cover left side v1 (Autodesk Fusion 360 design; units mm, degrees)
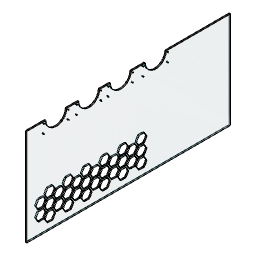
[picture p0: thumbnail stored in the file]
sketch "Sketch1" plane through (0, 0, 0) normal (1, 0, 0) x axis (0, 1, 0)
  line L1 (-390, -185) -> (-390, 185)
  line L2 (390, -185) -> (-390, -185)
  line L3 (390, 185) -> (390, -185)
  line L4 (-317, 185) -> (-390, 185)
  line L5 (-191, 185) -> (-237, 185)
  line L6 (-70, 185) -> (-111, 185)
  line L7 (64, 185) -> (10, 185)
  line L8 (390, 185) -> (144, 185)
  line L9 (-319.9278, -100.8334) -> (-309.9359, -83.5082)
  line L10 (-344.9359, -63.5082) -> (-324.9359, -63.4989)
  line L11 (-324.9197, -138.1399) -> (-344.9197, -138.1492)
  line L12 (-279.9278, -140.8147) -> (-289.9197, -158.1399)
  line L13 (-289.9359, -123.4989) -> (-279.9278, -140.8147)
  line L14 (25.0803, -98.1399) -> (5.0803, -98.1492)
  line L15 (-344.9359, -63.5082) -> (-324.9359, -63.4989)
  line L16 (-64.9197, -98.1492) -> (-74.9278, -80.8334)
  line L17 (-169.9197, -158.1492) -> (-179.9278, -140.8334)
  line L18 (5.0641, -103.5082) -> (25.0641, -103.4989)
  line L19 (-39.9278, -100.8334) -> (-29.9359, -83.5082)
  line L20 (-34.9278, -80.8147) -> (-44.9197, -98.1399)
  line L21 (-174.9278, -120.8147) -> (-184.9197, -138.1399)
  line L22 (-319.9278, -60.8334) -> (-309.9359, -43.5082)
  line L23 (-244.9278, -120.8147) -> (-254.9197, -138.1399)
  line L24 (-214.9278, -120.8334) -> (-204.9359, -103.5082)
  line L25 (-289.9197, -158.1399) -> (-309.9197, -158.1492)
  line L26 (-354.9278, -80.8334) -> (-344.9359, -63.5082)
  line L27 (-354.9278, -80.8334) -> (-344.9359, -63.5082)
  line L28 (-34.9278, -80.8147) -> (-44.9197, -98.1399)
  line L29 (-284.9278, -80.8334) -> (-274.9359, -63.5082)
  line L30 (-99.9359, -123.5082) -> (-79.9359, -123.4989)
  line L31 (-309.9197, -78.1492) -> (-319.9278, -60.8334)
  line L32 (-274.9197, -138.1492) -> (-284.9278, -120.8334)
  line L33 (-309.9359, -83.5082) -> (-289.9359, -83.4989)
  line L34 (-79.9359, -83.4989) -> (-69.9278, -100.8147)
  line L35 (-209.9278, -140.8147) -> (-219.9197, -158.1399)
  line L36 (-44.9359, -63.4989) -> (-34.9278, -80.8147)
  line L37 (-64.9359, -63.5082) -> (-44.9359, -63.4989)
  line L38 (-174.9278, -80.8147) -> (-184.9197, -98.1399)
  line L39 (-184.9359, -103.4989) -> (-174.9278, -120.8147)
  line L40 (-324.9197, -98.1399) -> (-344.9197, -98.1492)
  line L41 (-344.9359, -103.5082) -> (-324.9359, -103.4989)
  line L42 (-219.9197, -158.1399) -> (-239.9197, -158.1492)
  line L43 (25.0803, -138.1399) -> (5.0803, -138.1492)
  line L44 (60.0803, -158.1399) -> (40.0803, -158.1492)
  line L45 (-314.9278, -120.8147) -> (-324.9197, -138.1399)
  line L46 (-219.9197, -118.1399) -> (-239.9197, -118.1492)
  line L47 (-324.9359, -63.4989) -> (-314.9278, -80.8147)
  line L48 (-74.9278, -80.8334) -> (-64.9359, -63.5082)
  line L49 (-209.9278, -140.8147) -> (-219.9197, -158.1399)
  line L50 (-284.9278, -120.8334) -> (-274.9359, -103.5082)
  line L51 (-239.9197, -118.1492) -> (-249.9278, -100.8334)
  line L52 (40.0803, -158.1492) -> (30.0722, -140.8334)
  line L53 (-74.9278, -80.8334) -> (-64.9359, -63.5082)
  line L54 (-79.9359, -43.4989) -> (-69.9278, -60.8147)
  line L55 (-69.9278, -60.8147) -> (-79.9197, -78.1399)
  line L56 (-169.9197, -118.1492) -> (-179.9278, -100.8334)
  line L57 (-319.9278, -140.8334) -> (-309.9359, -123.5082)
  line L58 (-184.9197, -98.1399) -> (-204.9197, -98.1492)
  line L59 (0.0722, -140.8147) -> (-9.9197, -158.1399)
  line L60 (-99.9359, -123.5082) -> (-79.9359, -123.4989)
  line L61 (-79.9197, -158.1399) -> (-99.9197, -158.1492)
  line L62 (-219.9359, -123.4989) -> (-209.9278, -140.8147)
  line L63 (-209.9278, -100.8147) -> (-219.9197, -118.1399)
  line L64 (-219.9197, -158.1399) -> (-239.9197, -158.1492)
  line L65 (-309.9197, -158.1492) -> (-319.9278, -140.8334)
  line L66 (40.0641, -123.5082) -> (60.0641, -123.4989)
  line L67 (-4.9278, -120.8334) -> (5.0641, -103.5082)
  line L68 (-289.9197, -78.1399) -> (-309.9197, -78.1492)
  line L69 (-309.9359, -123.5082) -> (-289.9359, -123.4989)
  line L70 (-344.9197, -98.1492) -> (-354.9278, -80.8334)
  line L71 (-179.9278, -140.8334) -> (-169.9359, -123.5082)
  line L72 (-344.9197, -138.1492) -> (-354.9278, -120.8334)
  line L73 (-289.9359, -123.4989) -> (-279.9278, -140.8147)
  line L74 (25.0803, -98.1399) -> (5.0803, -98.1492)
  line L75 (-219.9359, -123.4989) -> (-209.9278, -140.8147)
  line L76 (-274.9197, -98.1492) -> (-284.9278, -80.8334)
  line L77 (-184.9197, -138.1399) -> (-204.9197, -138.1492)
  line L78 (25.0641, -103.4989) -> (35.0722, -120.8147)
  line L79 (-289.9197, -158.1399) -> (-309.9197, -158.1492)
  line L80 (-354.9278, -120.8334) -> (-344.9359, -103.5082)
  line L81 (-309.9359, -123.5082) -> (-289.9359, -123.4989)
  line L82 (-279.9278, -60.8147) -> (-289.9197, -78.1399)
  line L83 (-179.9278, -140.8334) -> (-169.9359, -123.5082)
  line L84 (-174.9278, -80.8147) -> (-184.9197, -98.1399)
  line L85 (-204.9359, -103.5082) -> (-184.9359, -103.4989)
  line L86 (60.0803, -78.1399) -> (40.0803, -78.1492)
  line L87 (-289.9359, -83.4989) -> (-279.9278, -100.8147)
  line L88 (-114.9197, -138.1399) -> (-134.9197, -138.1492)
  line L89 (30.0722, -140.8334) -> (40.0641, -123.5082)
  line L90 (-279.9278, -100.8147) -> (-289.9197, -118.1399)
  line L91 (60.0803, -118.1399) -> (40.0803, -118.1492)
  line L92 (-289.9359, -43.4989) -> (-279.9278, -60.8147)
  line L93 (70.0722, -100.8147) -> (60.0803, -118.1399)
  line L94 (-319.9278, -140.8334) -> (-309.9359, -123.5082)
  line L95 (-239.9197, -158.1492) -> (-249.9278, -140.8334)
  line L96 (-179.9278, -100.8334) -> (-169.9359, -83.5082)
  line L97 (-239.9359, -123.5082) -> (-219.9359, -123.4989)
  line L98 (-114.9197, -98.1399) -> (-134.9197, -98.1492)
  line L99 (60.0641, -123.4989) -> (70.0722, -140.8147)
  line L100 (0.0722, -100.8147) -> (-9.9197, -118.1399)
  line L101 (-99.9197, -158.1492) -> (-109.9278, -140.8334)
  line L102 (-254.9359, -103.4989) -> (-244.9278, -120.8147)
  line L103 (-239.9359, -123.5082) -> (-219.9359, -123.4989)
  line L104 (-134.9359, -103.5082) -> (-114.9359, -103.4989)
  line L105 (-79.9197, -158.1399) -> (-99.9197, -158.1492)
  line L106 (-79.9197, -78.1399) -> (-99.9197, -78.1492)
  line L107 (-204.9197, -98.1492) -> (-214.9278, -80.8334)
  line L108 (5.0803, -138.1492) -> (-4.9278, -120.8334)
  line L109 (-279.9278, -140.8147) -> (-289.9197, -158.1399)
  line L110 (35.0722, -120.8147) -> (25.0803, -138.1399)
  line L111 (-134.9197, -138.1492) -> (-144.9278, -120.8334)
  line L112 (-114.9197, -98.1399) -> (-134.9197, -98.1492)
  line L113 (-109.9278, -140.8334) -> (-99.9359, -123.5082)
  line L114 (-244.9278, -80.8147) -> (-254.9197, -98.1399)
  line L115 (-219.9359, -83.4989) -> (-209.9278, -100.8147)
  line L116 (-219.9359, -43.4989) -> (-209.9278, -60.8147)
  line L117 (-4.9278, -80.8334) -> (5.0641, -63.5082)
  line L118 (-254.9359, -63.4989) -> (-244.9278, -80.8147)
  line L119 (25.0641, -63.4989) -> (35.0722, -80.8147)
  line L120 (-99.9197, -158.1492) -> (-109.9278, -140.8334)
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  point P2 (-390, 185)
  point P3 (-390, -185)
  point P4 (390, -185)
  point P1 (0, 0)
  point P6 (-317, 185)
  point P7 (-237, 185)
  point P8 (-191, 185)
  point P9 (-111, 185)
  point P10 (-70, 185)
  point P11 (10, 185)
  point P12 (64, 185)
  point P13 (144, 185)
  point P18 (-289.9197, -158.1399)
  point P20 (-309.9197, -158.1492)
  point P30 (-309.9197, -158.1492)
  point P37 (-289.9197, -158.1399)
  point P66 (-309.9197, -118.1492)
  point P73 (-289.9197, -118.1399)
  point P58 (-274.9197, -138.1492)
  point P60 (-254.9197, -138.1399)
  point P93 (-239.9197, -158.1492)
  point P96 (-219.9197, -158.1399)
  point P42 (-219.9197, -158.1399)
  point P70 (-239.9197, -158.1492)
  point P133 (-239.9197, -118.1492)
  point P139 (-219.9197, -118.1399)
  point P132 (-204.9197, -138.1492)
  point P137 (-184.9197, -138.1399)
  point P332 (-149.9197, -158.1399)
  point P338 (-169.9197, -158.1492)
  point P113 (-149.9197, -158.1399)
  point P336 (-169.9197, -158.1492)
  point P159 (-169.9197, -118.1492)
  point P160 (-149.9197, -118.1399)
  point P106 (-134.9197, -138.1492)
  point P108 (-114.9197, -138.1399)
  point P149 (-344.9197, -138.1492)
  point P150 (-324.9197, -138.1399)
  point P26 (-79.9197, -158.1399)
  point P243 (-99.9197, -158.1492)
  point P80 (-79.9197, -158.1399)
  point P239 (-99.9197, -158.1492)
  point P147 (-99.9197, -118.1492)
  point P155 (-79.9197, -118.1399)
  point P97 (-64.9197, -138.1492)
  point P100 (-44.9197, -138.1399)
  point P47 (-9.9197, -158.1399)
  point P49 (-29.9197, -158.1492)
  point P342 (-29.9197, -158.1492)
  point P352 (-9.9197, -158.1399)
  point P166 (-9.9197, -118.1399)
  point P170 (-29.9197, -118.1492)
  point P167 (5.0803, -138.1492)
  point P168 (25.0803, -138.1399)
  point P85 (60.0803, -158.1399)
  point P88 (40.0803, -158.1492)
  point P200 (40.0803, -158.1492)
  point P202 (60.0803, -158.1399)
  point P255 (40.0803, -118.1492)
  point P261 (60.0803, -118.1399)
  point P125 (-344.9197, -98.1492)
  point P127 (-324.9197, -98.1399)
  point P119 (-344.9197, -98.1492)
  point P218 (-324.9197, -98.1399)
  point P181 (-289.9197, -78.1399)
  point P183 (-309.9197, -78.1492)
  point P196 (-274.9197, -98.1492)
  point P326 (-254.9197, -98.1399)
  point P221 (-254.9197, -98.1399)
  point P233 (-274.9197, -98.1492)
  point P209 (-219.9197, -78.1399)
  point P254 (-239.9197, -78.1492)
  point P288 (-204.9197, -98.1492)
  point P293 (-184.9197, -98.1399)
  point P248 (-184.9197, -98.1399)
  point P303 (-204.9197, -98.1492)
  point P320 (-149.9197, -78.1399)
  point P321 (-169.9197, -78.1492)
  point P117 (-114.9197, -98.1399)
  point P296 (-134.9197, -98.1492)
  point P197 (-114.9197, -98.1399)
  point P278 (-134.9197, -98.1492)
  point P318 (-99.9197, -78.1492)
  point P323 (-79.9197, -78.1399)
  point P213 (-64.9197, -98.1492)
  point P224 (-44.9197, -98.1399)
  point P306 (-44.9197, -98.1399)
  point P309 (-64.9197, -98.1492)
  point P269 (-29.9197, -78.1492)
  point P273 (-9.9197, -78.1399)
  point P186 (5.0803, -98.1492)
  point P190 (25.0803, -98.1399)
  point P280 (25.0803, -98.1399)
  point P283 (5.0803, -98.1492)
  point P287 (60.0803, -78.1399)
  point P297 (40.0803, -78.1492)
  point P354 (-324, 177)
  point P357 (-324, 143)
  point P358 (-230, 177)
  point P359 (-230, 143)
  point P360 (-198, 177)
  point P361 (-198, 143)
  point P362 (-104, 143)
  point P363 (-104, 177)
  point P364 (-77, 143)
  point P365 (-77, 177)
  point P366 (17, 177)
  point P367 (17, 143)
  point P368 (57, 143)
  point P369 (57, 177)
  point P370 (151, 177)
  point P371 (151, 143)
  vertical L1
  perpendicular L1 L2
  perpendicular L2 L3
  perpendicular L1 L4
  parallel L4 L5
  parallel L5 L6
  parallel L6 L7
  horizontal L8
  dimension "d1" distance P2 P3 = 370
  dimension "d2" distance P3 P4 = 780
  dimension "d3" distance P1 L1 = 390 (= "( 780 / 2 ) * 1 mm")
  dimension "d4" distance P1 L2 = 185 (= "( 370 / 2 ) * 1 mm")
  dimension "d5" distance P2 P6 = 73
  dimension "d7" distance P6 P7 = 80
  dimension "d8" distance P8 P9 = 80
  dimension "d9" distance P10 P11 = 80
  dimension "d10" distance P7 P8 = 46
  dimension "d11" distance P9 P10 = 41
  dimension "d12" distance P12 P13 = 80
  dimension "d13" distance P11 P12 = 54
  dimension "d19" distance P18 P20 = 20
  dimension "d20" distance P30 P37 = 20
  dimension "d21" distance P66 P73 = 20
  dimension "d22" distance P58 P60 = 20
  dimension "d23" distance P93 P96 = 20
  dimension "d24" distance P42 P70 = 20
  dimension "d25" distance P133 P139 = 20
  dimension "d26" distance P132 P137 = 20
  dimension "d27" distance P332 P338 = 20
  dimension "d28" distance P113 P336 = 20
  dimension "d29" distance P159 P160 = 20
  dimension "d30" distance P106 P108 = 20
  dimension "d31" distance P149 P150 = 20
  dimension "d32" distance P26 P243 = 20
  dimension "d33" distance P80 P239 = 20
  dimension "d34" distance P147 P155 = 20
  dimension "d35" distance P97 P100 = 20
  dimension "d36" distance P47 P49 = 20
  dimension "d37" distance P342 P352 = 20
  dimension "d38" distance P166 P170 = 20
  dimension "d39" distance P167 P168 = 20
  dimension "d40" distance P85 P88 = 20
  dimension "d41" distance P200 P202 = 20
  dimension "d42" distance P255 P261 = 20
  dimension "d43" distance P125 P127 = 20
  dimension "d44" distance P119 P218 = 20
  dimension "d45" distance P181 P183 = 20
  dimension "d46" distance P196 P326 = 20
  dimension "d47" distance P221 P233 = 20
  dimension "d48" distance P209 P254 = 20
  dimension "d49" distance P288 P293 = 20
  dimension "d50" distance P248 P303 = 20
  dimension "d51" distance P320 P321 = 20
  dimension "d52" distance P117 P296 = 20
  dimension "d53" distance P197 P278 = 20
  dimension "d54" distance P318 P323 = 20
  dimension "d55" distance P213 P224 = 20
  dimension "d56" distance P306 P309 = 20
  dimension "d57" distance P269 P273 = 20
  dimension "d58" distance P186 P190 = 20
  dimension "d59" distance P280 P283 = 20
  dimension "d60" distance P287 P297 = 20
  dimension "d65" diameter = 4
  dimension "d66" distance L4 P354 = 8
  dimension "d67" distance = 8
  dimension "d68" distance = 15
  dimension "d69" diameter = 4
  dimension "d70" distance P354 P357 = 34
  dimension "d71" diameter = 4
  dimension "d72" diameter = 4
  dimension "d73" distance P358 P359 = 34
  dimension "d74" diameter = 4
  dimension "d75" diameter = 4
  dimension "d76" distance P360 P361 = 34
  dimension "d77" diameter = 4
  dimension "d78" diameter = 4
  dimension "d79" distance P362 P363 = 34
  dimension "d80" diameter = 4
  dimension "d81" diameter = 4
  dimension "d82" distance P364 P365 = 34
  dimension "d83" diameter = 4
  dimension "d84" diameter = 4
  dimension "d85" distance P366 P367 = 34
  dimension "d86" diameter = 4
  dimension "d87" diameter = 4
  dimension "d88" distance P368 P369 = 34
  dimension "d89" diameter = 4
  dimension "d90" diameter = 4
  dimension "d91" distance P370 P371 = 34
extrude "Extrude1" new body sketch "Sketch1" along normal blind 5
extrude "Extrude2" cut sketch "Sketch1" along normal blind 5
